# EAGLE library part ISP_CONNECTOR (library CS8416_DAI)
ISP Connector
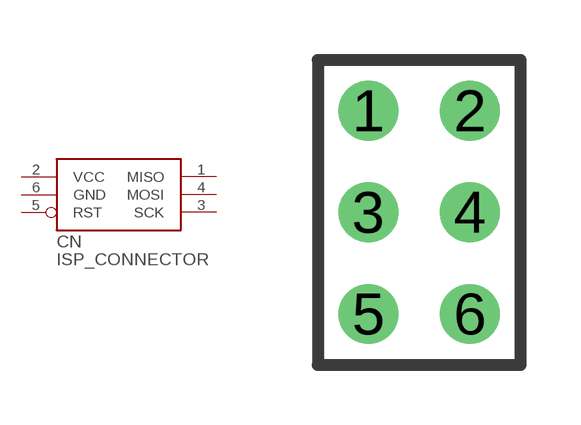
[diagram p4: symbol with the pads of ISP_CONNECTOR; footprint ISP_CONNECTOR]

Designator prefix CN

## ISP_CONNECTOR  [ISP_CONNECTOR]
1  MISO  pas
2  VCC  pwr
3  SCK  pas
4  MOSI  pas
5  RST  pas
6  GND  pwr

## Footprint ISP_CONNECTOR (pad centres in mm)
ISP Connector
drill 0.991 round: 1 -1.27,2.54; 2 1.27,2.54; 3 -1.27,0; 4 1.27,0; 5 -1.27,-2.54; 6 1.27,-2.54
